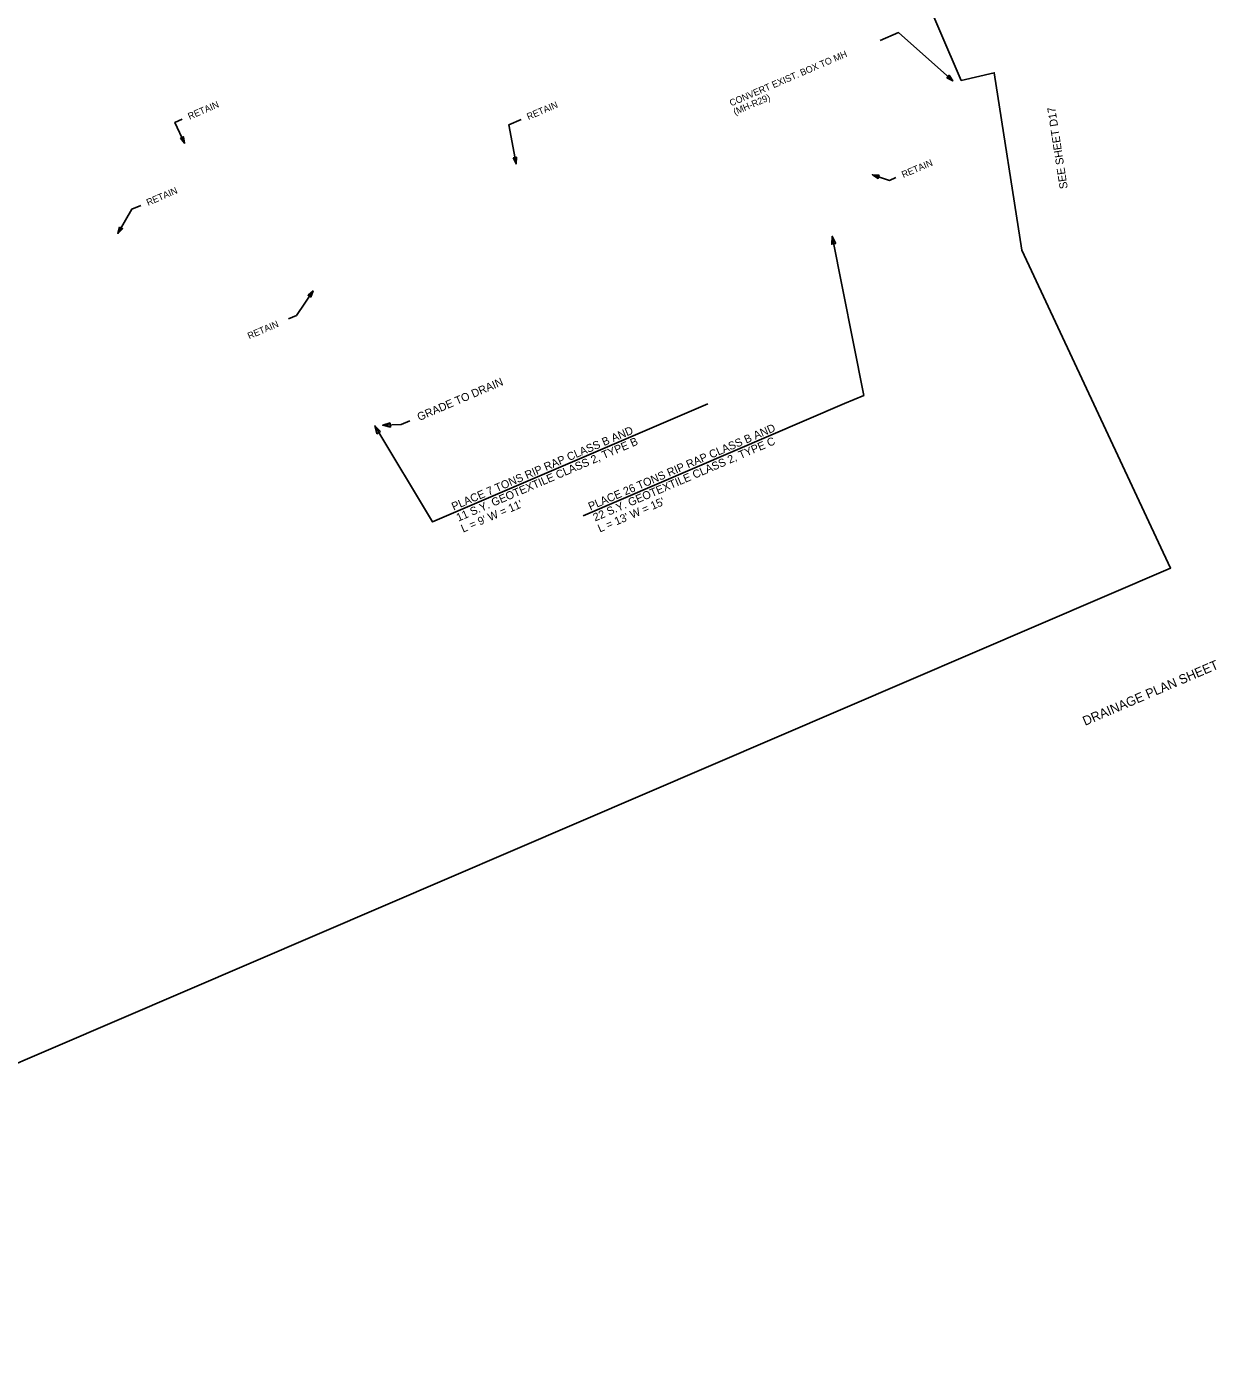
# Model space of a CAD drawing. Extents: x 1619705 to 1621490, y 1101723 to 1103701.
# Drawn here: x 1620598 to 1621490, y 1101793 to 1102790 of the extents above; entities that cross this region are included whole.
import ezdxf

# ---------------------------------------------------------------- set-up
doc = ezdxf.new("R2010")
doc.units = 0
for name, color, linetype in [('Level 2', 7, 'Continuous'), ('Level 20', 7, 'Continuous'), ('RD_HC_Data_Tic', 7, 'Continuous'), ('RFP', 7, 'Continuous')]:
    doc.layers.add(name, color=color, linetype=linetype)

msp = doc.modelspace()

# ---------------------------------------------------------------- linework, layer by layer
at = {"layer": 'Level 2'}
for p, q in [((1621108.94, 1102507.39), (1620913.09, 1102423.33)), ((1621211.41, 1102507.48), (1621015.57, 1102423.42))]:
    msp.add_line(p, q, dxfattribs=at)
for points in [[(1621238.07, 1102779.62), (1621251.96, 1102785.58), (1621292.48, 1102749.36)], [(1620714.98, 1102720.56), (1620709.56, 1102718.24), (1620716.82, 1102702.58)], [(1620968.96, 1102720.32), (1620959.78, 1102716.38), (1620965.18, 1102687.16)], [(1621249.89, 1102676.84), (1621245.01, 1102674.74), (1621232.34, 1102678.97)], [(1620683.89, 1102656.02), (1620677.37, 1102653.22), (1620666.71, 1102634.98)], [(1621211.41, 1102507.48), (1621225.75, 1102513.63), (1621202.16, 1102632.9)], [(1620794.56, 1102570.93), (1620800.56, 1102573.51), (1620813.15, 1102591.95)], [(1620885.57, 1102494.58), (1620879.21, 1102491.85), (1620865.25, 1102491.21)], [(1620913.09, 1102423.33), (1620902.5, 1102418.79), (1620859.33, 1102490.69)]]:
    msp.add_lwpolyline(points, dxfattribs=at)
for points in [[(1621288.02, 1102751.61), (1621292.48, 1102749.36), (1621289.74, 1102753.54)], [(1620713.61, 1102706.42), (1620716.82, 1102702.58), (1620715.96, 1102707.51)], [(1620963.03, 1102691.68), (1620965.18, 1102687.16), (1620965.57, 1102692.15)], [(1621237.33, 1102678.67), (1621232.34, 1102678.97), (1621236.51, 1102676.22)], [(1620668.03, 1102639.81), (1620666.71, 1102634.98), (1620670.26, 1102638.5)], [(1621204.81, 1102627.52), (1621202.16, 1102632.9), (1621201.76, 1102626.91)], [(1620811.5, 1102587.23), (1620813.15, 1102591.95), (1620809.36, 1102588.69)], [(1620863.65, 1102486.52), (1620859.33, 1102490.69), (1620860.99, 1102484.92)], [(1620870.97, 1102493.03), (1620865.25, 1102491.21), (1620871.11, 1102489.92)]]:
    msp.add_lwpolyline(points, close=True, dxfattribs=at)
at = {"layer": 'RFP'}
msp.add_lwpolyline([(1620077.33, 1101792.57), (1621455.74, 1102384.16), (1621344.3, 1102622.52), (1621323.62, 1102755.47), (1621298.88, 1102749.66), (1621097.02, 1103220), (1620951.48, 1103157.13), (1620938.43, 1103188.78), (1619705.25, 1102659.52)], close=True, dxfattribs=at)
msp.add_lwpolyline([(1620077.33, 1101792.57), (1621455.74, 1102384.16), (1621344.3, 1102622.52), (1621323.62, 1102755.47), (1621298.88, 1102749.66), (1621097.02, 1103220), (1620951.48, 1103157.13), (1620938.43, 1103188.78), (1619705.25, 1102659.52)], close=True, dxfattribs=at)
msp.add_lwpolyline([(1620077.33, 1101792.57), (1621455.74, 1102384.16), (1621344.3, 1102622.52), (1621323.62, 1102755.47), (1621298.88, 1102749.66), (1621097.02, 1103220), (1620951.48, 1103157.13), (1620938.43, 1103188.78), (1619705.25, 1102659.52)], close=True, dxfattribs=at)
msp.add_lwpolyline([(1620077.33, 1101792.57), (1621455.74, 1102384.16), (1621344.3, 1102622.52), (1621323.62, 1102755.47), (1621298.88, 1102749.66), (1621097.02, 1103220), (1620951.48, 1103157.13), (1620938.43, 1103188.78), (1619705.25, 1102659.52)], close=True, dxfattribs=at)
msp.add_lwpolyline([(1620077.33, 1101792.57), (1621455.74, 1102384.16), (1621344.3, 1102622.52), (1621323.62, 1102755.47), (1621298.88, 1102749.66), (1621097.02, 1103220), (1620951.48, 1103157.13), (1620938.43, 1103188.78), (1619705.25, 1102659.52)], close=True, dxfattribs=at)

# ---------------------------------------------------------------- texts
at = {"layer": 'Level 2'}
for s, height, p in [('CONVERT EXIST. BOX TO MH', 5, (1621126.5, 1102730.21)), ('RETAIN', 5, (1620720.56, 1102720.24)), ('RETAIN', 5, (1620974.54, 1102719.99)), ('(MH-R29)', 5, (1621129.34, 1102723.59)), ('RETAIN', 5, (1621255.47, 1102676.51)), ('RETAIN', 5, (1620689.47, 1102655.69)), ('RETAIN', 5, (1620765.26, 1102555.64)), ('GRADE TO DRAIN', 6, (1620892.68, 1102494.37)), ('PLACE 7 TONS RIP RAP CLASS B AND', 6, (1620918.43, 1102427.25)), ('PLACE 26 TONS RIP RAP CLASS B AND', 6, (1621020.9, 1102427.34)), ('11 S.Y. GEOTEXTILE CLASS 2, TYPE B', 6, (1620921.98, 1102418.98)), ('22 S.Y. GEOTEXTILE CLASS 2, TYPE C', 6, (1621024.45, 1102419.07)), ("L = 9' W = 11'", 6, (1620925.53, 1102410.71)), ("L = 13' W = 15'", 6, (1621028, 1102410.8))]:
    msp.add_text(s, height=height, rotation=23.22835, dxfattribs=at).set_placement(p)
at = {"layer": 'Level 20'}
msp.add_text('DRAINAGE PLAN SHEET', height=6.9833, rotation=23.22835, dxfattribs=at).set_placement((1621391.69, 1102265.91))
at = {"layer": 'RD_HC_Data_Tic'}
msp.add_text('SEE SHEET D17', height=6, rotation=98.84251, dxfattribs=at).set_placement((1621378.72, 1102668.86))

doc.saveas('drawing.dxf')
